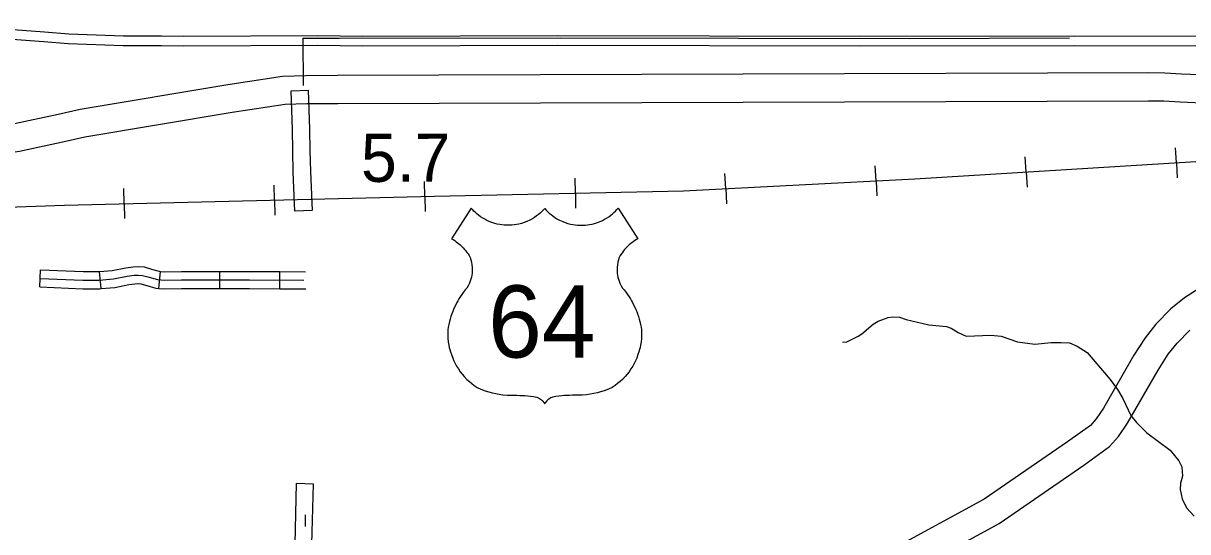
# Model space of a CAD drawing. Extents: x 1374139 to 1377472, y 1168351 to 1170484.
# Drawn here: x 1376137.2 to 1376341.5, y 1168985.6 to 1169074.9 of the extents above; entities that cross this region are included whole.
import ezdxf

# ---------------------------------------------------------------- set-up
doc = ezdxf.new("R2010")
doc.units = 0
doc.layers.add('Default', color=7, linetype='Continuous')

msp = doc.modelspace()

# ---------------------------------------------------------------- linework, layer by layer
at = {"layer": 'Default'}
for p, q in [((1376184.21, 1169063.03), (1376187.21, 1169063.12)), ((1376313.17, 1169048.76), (1376313.01, 1169051.4)), ((1376339.52, 1169050.38), (1376339.36, 1169053.02)), ((1376286.82, 1169047.21), (1376286.68, 1169049.85)), ((1376339.52, 1169050.38), (1376339.68, 1169047.75)), ((1376234.07, 1169045.05), (1376234.01, 1169047.69)), ((1376260.45, 1169045.84), (1376260.32, 1169048.48)), ((1376313.17, 1169048.76), (1376313.33, 1169046.13)), ((1376154.89, 1169043.21), (1376154.83, 1169045.85)), ((1376181.28, 1169043.85), (1376181.22, 1169046.48)), ((1376207.67, 1169044.48), (1376207.61, 1169047.12)), ((1376260.45, 1169045.84), (1376260.59, 1169043.2)), ((1376286.82, 1169047.21), (1376286.95, 1169044.57)), ((1376154.89, 1169043.21), (1376154.95, 1169040.57)), ((1376181.28, 1169043.85), (1376181.34, 1169041.21)), ((1376207.67, 1169044.48), (1376207.74, 1169041.84)), ((1376234.07, 1169045.05), (1376234.12, 1169042.41)), ((1376187.88, 1169042.03), (1376184.88, 1169041.9)), ((1376184.88, 1169041.9), (1376184.88, 1169041.9)), ((1376140.12, 1169028.59), (1376140.25, 1169031.59)), ((1376150.86, 1169028.3), (1376150.61, 1169031.29)), ((1376160.97, 1169028.33), (1376161.27, 1169031.32)), ((1376171.68, 1169028.3), (1376171.68, 1169031.3)), ((1376182.23, 1169028.27), (1376182.25, 1169031.27)), ((1376188.11, 1168993.96), (1376185.11, 1168994.04))]:
    msp.add_line(p, q, dxfattribs=at)
for points in [[(1376116.33, 1169076.71), (1376127.16, 1169074.85), (1376135.42, 1169073.77), (1376140.95, 1169073.36), (1376145.19, 1169073.05), (1376154.8, 1169072.7), (1376161.44, 1169072.67), (1376165.41, 1169072.6), (1376188.84, 1169072.74), (1376196.78, 1169072.63), (1376230.97, 1169072.74), (1376284.13, 1169072.63), (1376321.67, 1169072.7), (1376351.52, 1169072.63), (1376361.33, 1169072.74), (1376365.1, 1169072.88), (1376368.41, 1169073.13), (1376372.43, 1169073.65), (1376375.93, 1169074.17), (1376378.93, 1169074.69), (1376380.91, 1169075.03)], [(1376116.01, 1169075.04), (1376126.91, 1169073.17), (1376135.25, 1169072.08), (1376140.82, 1169071.66), (1376145.1, 1169071.35), (1376154.76, 1169071), (1376161.42, 1169070.97), (1376165.4, 1169070.9), (1376188.83, 1169071.04), (1376196.77, 1169070.93), (1376230.97, 1169071.04), (1376284.13, 1169070.93), (1376321.67, 1169071), (1376351.53, 1169070.93), (1376361.37, 1169071.04), (1376365.19, 1169071.18), (1376368.59, 1169071.44), (1376372.66, 1169071.96), (1376376.2, 1169072.49), (1376379.22, 1169073.01), (1376381.23, 1169073.36), (1376383.73, 1169073.88), (1376391.01, 1169075.79)], [(1376186.27, 1169072.25), (1376192.63, 1169072.26), (1376231.54, 1169072.32), (1376262.68, 1169072.29), (1376292.65, 1169072.19), (1376320.77, 1169072.34)], [(1376186.27, 1169072.25), (1376186.3, 1169063.93)], [(1376147.18, 1169059.79), (1376173.09, 1169064.13), (1376182.72, 1169065.61), (1376186.86, 1169065.73), (1376192.37, 1169065.76), (1376334.69, 1169066.23), (1376337.5, 1169066.18), (1376340.41, 1169066), (1376346.76, 1169065.76), (1376354.52, 1169065.76), (1376389.16, 1169067.07), (1376414.01, 1169067.37), (1376417.51, 1169067.09)], [(1376416.66, 1169062.14), (1376413.84, 1169062.36), (1376389.28, 1169062.07), (1376354.62, 1169060.76), (1376346.66, 1169060.76), (1376340.16, 1169061.01), (1376337.3, 1169061.19), (1376334.65, 1169061.23), (1376192.39, 1169060.76), (1376186.94, 1169060.73), (1376183.17, 1169060.62), (1376173.88, 1169059.19), (1376148.01, 1169054.86)], [(1376184.51, 1169052.48), (1376184.42, 1169056.2), (1376184.21, 1169063.03)], [(1376187.21, 1169063.12), (1376187.42, 1169056.28), (1376187.51, 1169052.55)], [(1375994.23, 1169061.13), (1376022.3, 1169061.2), (1376032.77, 1169060.78), (1376047.17, 1169060.01), (1376074.92, 1169058.41), (1376111.14, 1169056.15), (1376115.72, 1169055.93), (1376122.17, 1169055.84), (1376126.12, 1169056.05), (1376130.14, 1169056.42), (1376135.65, 1169057.27), (1376143.32, 1169058.93), (1376147.18, 1169059.79)], [(1375980.44, 1169055.83), (1376021.26, 1169049.25), (1376024.29, 1169048.81), (1376032.84, 1169048.04), (1376042.84, 1169047.18), (1376068.56, 1169045.3), (1376103.8, 1169042.51), (1376110.96, 1169042.16), (1376115.25, 1169042.16), (1376124.29, 1169042.25), (1376144.46, 1169042.96), (1376209.36, 1169044.52), (1376253.07, 1169045.46), (1376293.61, 1169047.56), (1376378.04, 1169052.75), (1376397.45, 1169053.83), (1376425.66, 1169054.41), (1376486.36, 1169055.84), (1376597.43, 1169058.88)], [(1375980.44, 1169055.83), (1376021.26, 1169049.25), (1376024.29, 1169048.81), (1376032.84, 1169048.04), (1376042.84, 1169047.18), (1376068.56, 1169045.3), (1376103.8, 1169042.51), (1376110.96, 1169042.16), (1376115.25, 1169042.16), (1376124.29, 1169042.25), (1376144.46, 1169042.96), (1376209.36, 1169044.52), (1376253.07, 1169045.46), (1376293.61, 1169047.56), (1376378.04, 1169052.75), (1376397.45, 1169053.83), (1376425.66, 1169054.41), (1376486.36, 1169055.84), (1376597.43, 1169058.88)], [(1376148.01, 1169054.86), (1376144.39, 1169054.05), (1376136.56, 1169052.35), (1376130.75, 1169051.46), (1376126.48, 1169051.07), (1376122.27, 1169050.84), (1376115.56, 1169050.93), (1376110.87, 1169051.16), (1376074.62, 1169053.42), (1376046.89, 1169055.02), (1376032.54, 1169055.78), (1376022.21, 1169056.2), (1375994.12, 1169056.13)], [(1376184.88, 1169041.9), (1376184.59, 1169048.76), (1376184.51, 1169052.48)], [(1376187.51, 1169052.55), (1376187.59, 1169048.86), (1376187.88, 1169042.03)], [(1376228.69, 1169042.37), (1376228.43, 1169042.07), (1376228.18, 1169041.82), (1376227.89, 1169041.55), (1376227.58, 1169041.28), (1376227.28, 1169041.05), (1376226.92, 1169040.8), (1376226.53, 1169040.56), (1376226.09, 1169040.32), (1376225.53, 1169040.06), (1376225.1, 1169039.89), (1376224.62, 1169039.73), (1376224.17, 1169039.62), (1376223.76, 1169039.53), (1376223.33, 1169039.47), (1376222.93, 1169039.42), (1376222.39, 1169039.4), (1376221.95, 1169039.4), (1376221.56, 1169039.43), (1376221.19, 1169039.47), (1376220.82, 1169039.52), (1376220.36, 1169039.62), (1376219.92, 1169039.73), (1376219.4, 1169039.9), (1376218.95, 1169040.08), (1376218.55, 1169040.26), (1376218.18, 1169040.46), (1376217.83, 1169040.66), (1376217.45, 1169040.91), (1376217.1, 1169041.17), (1376216.8, 1169041.41), (1376216.54, 1169041.64), (1376216.28, 1169041.89), (1376216.03, 1169042.16), (1376215.82, 1169042.4), (1376212.36, 1169037.05), (1376212.61, 1169036.9), (1376212.9, 1169036.71), (1376213.18, 1169036.51), (1376213.55, 1169036.22), (1376213.85, 1169035.96), (1376214.11, 1169035.72), (1376214.38, 1169035.44), (1376214.65, 1169035.14), (1376214.85, 1169034.9), (1376215.05, 1169034.65), (1376215.24, 1169034.37), (1376215.43, 1169034.08), (1376215.61, 1169033.74), (1376215.75, 1169033.33), (1376215.85, 1169032.91), (1376215.92, 1169032.47), (1376215.97, 1169032.06), (1376215.98, 1169031.67), (1376215.97, 1169031.29), (1376215.95, 1169031), (1376215.9, 1169030.63), (1376215.83, 1169030.29), (1376215.73, 1169029.92), (1376215.63, 1169029.59), (1376215.49, 1169029.23), (1376215.26, 1169028.76), (1376215.03, 1169028.38), (1376214.75, 1169028.05), (1376214.41, 1169027.62), (1376214.14, 1169027.23), (1376213.88, 1169026.85), (1376213.65, 1169026.48), (1376213.45, 1169026.14), (1376213.27, 1169025.83), (1376213.08, 1169025.45), (1376212.87, 1169025.02), (1376212.68, 1169024.59), (1376212.55, 1169024.27), (1376212.4, 1169023.87), (1376212.23, 1169023.37), (1376212.1, 1169022.95), (1376211.97, 1169022.5), (1376211.85, 1169021.97), (1376211.78, 1169021.51), (1376211.72, 1169021.02), (1376211.69, 1169020.49), (1376211.69, 1169019.99), (1376211.71, 1169019.5), (1376211.77, 1169018.92), (1376211.86, 1169018.38), (1376211.95, 1169017.97), (1376212.04, 1169017.61), (1376212.16, 1169017.2), (1376212.32, 1169016.69), (1376212.55, 1169016.07), (1376212.75, 1169015.62), (1376212.97, 1169015.15), (1376213.22, 1169014.69), (1376213.55, 1169014.17), (1376213.89, 1169013.68), (1376214.21, 1169013.26), (1376214.58, 1169012.83), (1376215.06, 1169012.34), (1376215.47, 1169011.96), (1376215.89, 1169011.61)], [(1376228.69, 1169042.37), (1376228.95, 1169042.07), (1376229.2, 1169041.82), (1376229.49, 1169041.55), (1376229.8, 1169041.28), (1376230.1, 1169041.05), (1376230.46, 1169040.8), (1376230.85, 1169040.56), (1376231.29, 1169040.32), (1376231.85, 1169040.06), (1376232.28, 1169039.89), (1376232.76, 1169039.73), (1376233.21, 1169039.62), (1376233.62, 1169039.53), (1376234.05, 1169039.47), (1376234.45, 1169039.42), (1376234.99, 1169039.4), (1376235.43, 1169039.4), (1376235.82, 1169039.43), (1376236.18, 1169039.47), (1376236.55, 1169039.52), (1376237.02, 1169039.62), (1376237.45, 1169039.73), (1376237.98, 1169039.9), (1376238.43, 1169040.08), (1376238.83, 1169040.26), (1376239.2, 1169040.46), (1376239.54, 1169040.66), (1376239.93, 1169040.91), (1376240.28, 1169041.17), (1376240.58, 1169041.41), (1376240.84, 1169041.64), (1376241.1, 1169041.89), (1376241.35, 1169042.16), (1376241.56, 1169042.4), (1376245.02, 1169037.05), (1376244.77, 1169036.9), (1376244.48, 1169036.71), (1376244.2, 1169036.51), (1376243.83, 1169036.22), (1376243.53, 1169035.96), (1376243.27, 1169035.72), (1376243, 1169035.44), (1376242.72, 1169035.14), (1376242.53, 1169034.9), (1376242.33, 1169034.65), (1376242.14, 1169034.37), (1376241.94, 1169034.08), (1376241.77, 1169033.74), (1376241.63, 1169033.33), (1376241.53, 1169032.91), (1376241.45, 1169032.47), (1376241.41, 1169032.06), (1376241.4, 1169031.67), (1376241.41, 1169031.29), (1376241.43, 1169031), (1376241.48, 1169030.63), (1376241.55, 1169030.29), (1376241.65, 1169029.92), (1376241.75, 1169029.59), (1376241.89, 1169029.23), (1376242.12, 1169028.76), (1376242.35, 1169028.38), (1376242.63, 1169028.05), (1376242.97, 1169027.62), (1376243.24, 1169027.23), (1376243.5, 1169026.85), (1376243.73, 1169026.48), (1376243.93, 1169026.14), (1376244.11, 1169025.83), (1376244.3, 1169025.45), (1376244.51, 1169025.02), (1376244.7, 1169024.59), (1376244.83, 1169024.27), (1376244.98, 1169023.87), (1376245.15, 1169023.37), (1376245.28, 1169022.95), (1376245.41, 1169022.5), (1376245.52, 1169021.97), (1376245.6, 1169021.51), (1376245.66, 1169021.02), (1376245.69, 1169020.49), (1376245.69, 1169019.99), (1376245.67, 1169019.5), (1376245.61, 1169018.92), (1376245.52, 1169018.38), (1376245.43, 1169017.97), (1376245.34, 1169017.61), (1376245.22, 1169017.2), (1376245.06, 1169016.69), (1376244.83, 1169016.07), (1376244.63, 1169015.62), (1376244.41, 1169015.15), (1376244.15, 1169014.69), (1376243.83, 1169014.17), (1376243.49, 1169013.68), (1376243.17, 1169013.26), (1376242.8, 1169012.83), (1376242.32, 1169012.34), (1376241.91, 1169011.96), (1376241.49, 1169011.61)], [(1376140.25, 1169031.59), (1376147.71, 1169031.27), (1376150.47, 1169031.27), (1376150.61, 1169031.29)], [(1376150.61, 1169031.29), (1376152.83, 1169031.47), (1376155.19, 1169031.94), (1376156.5, 1169032.13), (1376157.42, 1169032.17), (1376158.4, 1169032.09), (1376159.7, 1169031.72), (1376161.03, 1169031.34), (1376161.27, 1169031.32)], [(1376161.27, 1169031.32), (1376162, 1169031.25), (1376164.95, 1169031.3), (1376171.68, 1169031.3)], [(1376171.68, 1169031.3), (1376176.91, 1169031.3), (1376182.25, 1169031.27)], [(1376182.25, 1169031.27), (1376186.71, 1169031.24)], [(1376140.19, 1169030.09), (1376147.68, 1169029.77), (1376150.54, 1169029.77), (1376153.04, 1169029.98), (1376155.45, 1169030.46), (1376156.64, 1169030.64), (1376157.39, 1169030.67), (1376158.13, 1169030.61), (1376159.29, 1169030.28), (1376160.75, 1169029.86), (1376161.94, 1169029.75), (1376164.96, 1169029.8), (1376176.9, 1169029.8), (1376186.46, 1169029.75)], [(1376150.86, 1169028.3), (1376153.25, 1169028.5), (1376155.71, 1169028.98), (1376156.78, 1169029.14), (1376157.36, 1169029.17), (1376157.86, 1169029.13), (1376158.88, 1169028.84), (1376160.47, 1169028.39), (1376160.97, 1169028.33)], [(1376140.12, 1169028.59), (1376147.64, 1169028.27), (1376150.6, 1169028.27), (1376150.86, 1169028.3)], [(1376160.97, 1169028.33), (1376161.88, 1169028.24), (1376164.97, 1169028.3), (1376171.68, 1169028.3)], [(1376171.68, 1169028.3), (1376176.9, 1169028.3), (1376182.23, 1169028.27)], [(1376182.23, 1169028.27), (1376186.76, 1169028.24)], [(1376343.06, 1169028.03), (1376340.93, 1169026.64), (1376338.55, 1169024.73), (1376335.88, 1169022.05), (1376334.01, 1169019.66), (1376332.04, 1169016.59), (1376326.7, 1169007.31), (1376325.42, 1169005.4), (1376324.42, 1169004.27), (1376320.41, 1169001.35), (1376305.8, 1168991.31), (1376289.45, 1168982.4)], [(1376280.92, 1169018.88), (1376281.67, 1169018.96), (1376283.7, 1169019.94), (1376284.33, 1169020.34), (1376286.32, 1169022.04), (1376287.19, 1169022.57), (1376288.93, 1169023.22), (1376289.72, 1169023.32), (1376290.92, 1169023.28), (1376292.1, 1169022.85), (1376296.08, 1169021.91), (1376299.21, 1169021.64), (1376300.03, 1169021.36), (1376301.24, 1169020.58), (1376302.63, 1169019.95), (1376306.99, 1169020.12), (1376308.79, 1169019.93), (1376311.66, 1169018.94), (1376314.67, 1169018.54), (1376317.54, 1169018.85), (1376319.28, 1169018.84), (1376320.78, 1169018.74), (1376322.12, 1169018.16), (1376323.87, 1169017.05), (1376327.92, 1169012.34), (1376329.17, 1169010.55), (1376330.1, 1169009), (1376331.52, 1169006.01), (1376332.52, 1169004.76), (1376334.35, 1169002.95), (1376338.42, 1168999.92), (1376339.97, 1168998.02), (1376340.48, 1168996.97), (1376340.57, 1168995.35), (1376340.24, 1168994.12), (1376340.16, 1168992.98), (1376340.5, 1168991.36), (1376341.31, 1168989.78), (1376342.61, 1168988.3)], [(1376292.11, 1168978.15), (1376308.41, 1168987.05), (1376323.3, 1168997.27), (1376327.79, 1169000.55), (1376329.38, 1169002.32), (1376330.95, 1169004.67), (1376336.32, 1169013.99), (1376338.09, 1169016.77), (1376339.63, 1169018.73), (1376341.9, 1169021)], [(1376215.89, 1169011.61), (1376216.32, 1169011.28), (1376216.84, 1169010.94), (1376217.5, 1169010.65), (1376218.26, 1169010.35), (1376218.89, 1169010.15), (1376219.45, 1169009.99), (1376220.09, 1169009.85), (1376220.69, 1169009.74), (1376221.33, 1169009.65), (1376222.14, 1169009.58), (1376222.76, 1169009.56), (1376223.29, 1169009.56), (1376223.8, 1169009.55), (1376224.32, 1169009.54), (1376224.81, 1169009.51), (1376225.23, 1169009.49), (1376225.65, 1169009.45), (1376226.19, 1169009.39), (1376226.72, 1169009.33), (1376227.03, 1169009.28), (1376227.29, 1169009.23), (1376227.61, 1169009.1), (1376227.79, 1169009), (1376227.95, 1169008.9), (1376228.16, 1169008.73), (1376228.37, 1169008.52), (1376228.54, 1169008.3), (1376228.69, 1169008.05)], [(1376241.49, 1169011.61), (1376241.06, 1169011.28), (1376240.54, 1169010.94), (1376239.88, 1169010.65), (1376239.12, 1169010.35), (1376238.49, 1169010.15), (1376237.93, 1169009.99), (1376237.29, 1169009.85), (1376236.69, 1169009.74), (1376236.05, 1169009.65), (1376235.24, 1169009.58), (1376234.62, 1169009.56), (1376234.09, 1169009.56), (1376233.58, 1169009.55), (1376233.06, 1169009.54), (1376232.57, 1169009.51), (1376232.15, 1169009.49), (1376231.72, 1169009.45), (1376231.19, 1169009.39), (1376230.66, 1169009.33), (1376230.35, 1169009.28), (1376230.09, 1169009.23), (1376229.77, 1169009.1), (1376229.59, 1169009), (1376229.43, 1169008.9), (1376229.22, 1169008.73), (1376229.01, 1169008.52), (1376228.84, 1169008.3), (1376228.69, 1169008.05)], [(1376185.11, 1168994.04), (1376184.83, 1168983.49)], [(1376187.83, 1168983.4), (1376188.11, 1168993.96)], [(1376186.64, 1168988.55), (1376186.65, 1168986.49)]]:
    msp.add_lwpolyline(points, dxfattribs=at)

# ---------------------------------------------------------------- texts
msp.add_text('5.7', height=8.448, rotation=0.1892, dxfattribs=at).set_placement((1376196.47, 1169047.02))
msp.add_text('64', height=12.672, dxfattribs=at).set_placement((1376218.77, 1169016.18))

doc.saveas('drawing.dxf')
